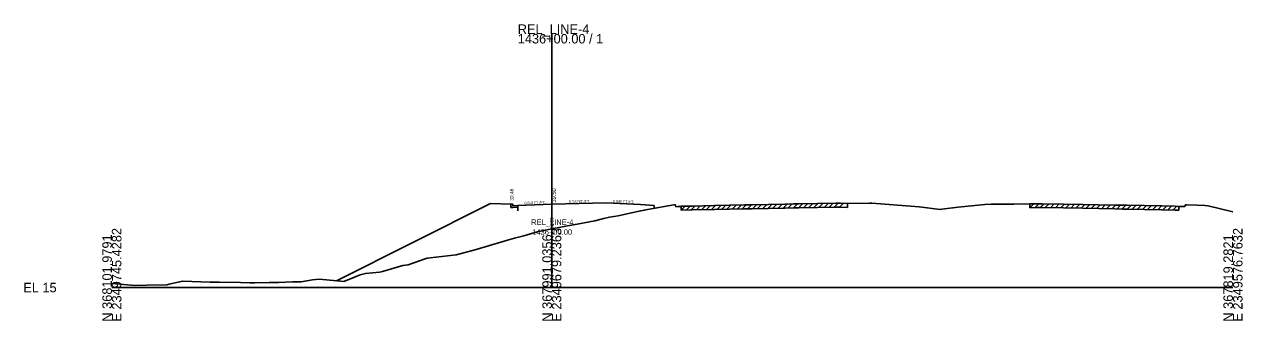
# Model space of a CAD drawing. Extents: x -26 to 2350146, y -10 to 368200.
# Drawn here: x 974.3 to 1332, y 7490.3 to 7577.2 of the extents above; entities that cross this region are included whole.
import ezdxf

# ---------------------------------------------------------------- set-up
doc = ezdxf.new("R2010")
doc.units = 0
for name, color, linetype in [('RD_GPK_XS_Cell', 7, 'Continuous'), ('RD_XS_CurbBase', 7, 'Continuous'), ('RD_XS_CurbFront', 7, 'Continuous'), ('RD_XS_CurbTop', 7, 'Continuous'), ('RD_XS_EarthShd', 7, 'Continuous'), ('RD_XS_ExGround', 7, 'Continuous'), ('RD_XS_ExPaveRet', 7, 'Continuous'), ('RD_XS_MatchLine', 7, 'Continuous'), ('RD_XS_Pave', 7, 'Continuous'), ('RD_XS_PaveShd', 7, 'Continuous'), ('RD_XS_TieSlope', 7, 'Continuous'), ('RD_XS_TX_Elev_EX', 7, 'Continuous'), ('RD_XS_TX_Elev_PR', 7, 'Continuous'), ('RD_XS_TX_Slope', 7, 'Continuous'), ('RD_XS_TX_Station', 7, 'Continuous'), ('RD_XS_TX_TOC', 7, 'Continuous')]:
    doc.layers.add(name, color=color, linetype=linetype)

msp = doc.modelspace()

# ---------------------------------------------------------------- linework, layer by layer
at = {"layer": 'RD_GPK_XS_Cell'}
for p, q in [((1129.19, 7500), (1129.19, 7574.41)), ((1000, 7500), (1129.19, 7500)), ((1129.19, 7500), (1329.19, 7500))]:
    msp.add_line(p, q, dxfattribs=at)
at = {"layer": 'RD_XS_CurbBase'}
for p, q in [((1117.19, 7524.5), (1117.19, 7523.5)), ((1117.19, 7523.5), (1117.69, 7523.5)), ((1117.69, 7523.5), (1119.19, 7523.58)), ((1119.19, 7522.52), (1119.19, 7523.58))]:
    msp.add_line(p, q, dxfattribs=at)
at = {"layer": 'RD_XS_CurbFront'}
msp.add_line((1119.19, 7523.58), (1119.19, 7524.08), dxfattribs=at)
at = {"layer": 'RD_XS_CurbTop'}
for p, q in [((1117.69, 7524.5), (1117.19, 7524.5)), ((1117.77, 7524), (1117.69, 7524.5)), ((1119.19, 7524.08), (1117.77, 7524)), ((1119.19, 7524.1), (1119.19, 7524.08))]:
    msp.add_line(p, q, dxfattribs=at)
at = {"layer": 'RD_XS_EarthShd'}
for p, q in [((1117.19, 7524.5), (1111.19, 7524.62)), ((1155.19, 7524.42), (1159.19, 7524.1))]:
    msp.add_line(p, q, dxfattribs=at)
at = {"layer": 'RD_XS_ExGround'}
msp.add_lwpolyline([(1000, 7501.23), (1006.95, 7500.56), (1010.29, 7500.75), (1016.12, 7500.81), (1016.78, 7500.96), (1020.71, 7501.91), (1028.9, 7501.55), (1031.62, 7501.55), (1037.79, 7501.45), (1040.49, 7501.41), (1041.96, 7501.42), (1046.16, 7501.5), (1048.93, 7501.45), (1053.02, 7501.68), (1054.52, 7501.72), (1055.57, 7501.73), (1058.89, 7502.26), (1060.89, 7502.42), (1063.02, 7502.27), (1068.15, 7501.82), (1071.22, 7503.03), (1072.9, 7503.74), (1074.44, 7504.15), (1078.54, 7504.53), (1079.06, 7504.65), (1079.45, 7504.76), (1085.42, 7506.5), (1086.96, 7506.71), (1092.01, 7508.4), (1092.63, 7508.63), (1099.4, 7509.37), (1101.11, 7509.58), (1106.27, 7510.97), (1109.62, 7511.97), (1116.21, 7513.88), (1118.22, 7514.5), (1120.93, 7515.17), (1124.89, 7516.34), (1129.19, 7517.19), (1133.78, 7518.08), (1136.61, 7518.59), (1141.84, 7519.57), (1144.47, 7520.28), (1146.12, 7520.65), (1148.67, 7521.09), (1155.24, 7522.47), (1156.36, 7522.72), (1156.75, 7522.79), (1157.32, 7522.9), (1165.04, 7524.25), (1165.47, 7524.24), (1165.63, 7523.73), (1166.22, 7523.75), (1166.88, 7523.78), (1167.12, 7523.86), (1169.98, 7523.92), (1170.43, 7523.93), (1176.92, 7524.06), (1185.73, 7524.23), (1186.33, 7524.25), (1188, 7524.29), (1197.56, 7524.48), (1200.16, 7524.54), (1201.71, 7524.56), (1212.65, 7524.74), (1213.91, 7524.72), (1215.98, 7524.69), (1222.43, 7524.8), (1222.87, 7524.8), (1223.18, 7524.78), (1235.82, 7523.74), (1237.06, 7523.64), (1243.26, 7522.94), (1243.75, 7523), (1248.53, 7523.61), (1256.32, 7524.34), (1258.19, 7524.51), (1264.83, 7524.51), (1269.58, 7524.58), (1271.3, 7524.59), (1273.12, 7524.61), (1279.42, 7524.51), (1285.04, 7524.41), (1294.52, 7524.21), (1296.8, 7524.15), (1298.12, 7524.13), (1308.2, 7523.95), (1312.23, 7523.86), (1313.3, 7523.83), (1313.49, 7523.78), (1315.03, 7523.75), (1315.22, 7524.23), (1315.61, 7524.24), (1318.64, 7524.18), (1320.94, 7524.12), (1321.89, 7523.99), (1329.19, 7522.21)], dxfattribs=at)
at = {"layer": 'RD_XS_ExPaveRet'}
for p, q in [((1167.12, 7522.72), (1168.29, 7523.88)), ((1167.12, 7522.72), (1167.12, 7523.86)), ((1168.62, 7522.75), (1169.79, 7523.92)), ((1170.12, 7522.78), (1171.29, 7523.95)), ((1170.43, 7522.79), (1176.92, 7522.92)), ((1171.62, 7522.81), (1172.79, 7523.98)), ((1173.12, 7522.84), (1174.29, 7524.01)), ((1174.62, 7522.87), (1175.79, 7524.04)), ((1176.12, 7522.9), (1177.29, 7524.07)), ((1176.92, 7522.92), (1185.73, 7523.09)), ((1177.62, 7522.93), (1178.79, 7524.1)), ((1179.12, 7522.96), (1180.29, 7524.13)), ((1180.62, 7522.99), (1181.79, 7524.15)), ((1182.12, 7523.02), (1183.29, 7524.18)), ((1183.62, 7523.05), (1184.79, 7524.21)), ((1185.12, 7523.08), (1186.29, 7524.25)), ((1185.73, 7523.09), (1186.33, 7523.1)), ((1186.33, 7523.1), (1188, 7523.15)), ((1186.62, 7523.11), (1187.79, 7524.28)), ((1188, 7523.15), (1197.56, 7523.34)), ((1188.12, 7523.15), (1189.29, 7524.32)), ((1189.62, 7523.18), (1190.79, 7524.35)), ((1191.12, 7523.21), (1192.29, 7524.38)), ((1192.62, 7523.24), (1193.79, 7524.41)), ((1194.12, 7523.27), (1195.29, 7524.44)), ((1195.62, 7523.3), (1196.79, 7524.47)), ((1197.12, 7523.33), (1198.29, 7524.5)), ((1197.56, 7523.34), (1200.16, 7523.39)), ((1198.62, 7523.36), (1199.79, 7524.53)), ((1200.12, 7523.39), (1201.28, 7524.55)), ((1200.16, 7523.39), (1201.71, 7523.42)), ((1201.62, 7523.42), (1202.78, 7524.58)), ((1201.71, 7523.42), (1212.65, 7523.59)), ((1203.12, 7523.44), (1204.28, 7524.6)), ((1204.62, 7523.46), (1205.78, 7524.63)), ((1206.12, 7523.49), (1207.28, 7524.65)), ((1207.62, 7523.51), (1208.78, 7524.67)), ((1209.12, 7523.54), (1210.28, 7524.7)), ((1210.62, 7523.56), (1211.78, 7524.72)), ((1212.12, 7523.58), (1213.27, 7524.73)), ((1212.65, 7523.59), (1213.91, 7523.58)), ((1213.62, 7523.58), (1214.74, 7524.71)), ((1213.91, 7523.58), (1215.98, 7523.54)), ((1215.98, 7524.69), (1215.98, 7523.54)), ((1269.58, 7523.43), (1270.73, 7524.59)), ((1269.58, 7523.43), (1269.58, 7524.58)), ((1269.58, 7523.43), (1271.3, 7523.45)), ((1271.08, 7523.45), (1272.23, 7524.6)), ((1271.3, 7523.45), (1273.12, 7523.47)), ((1272.58, 7523.46), (1273.72, 7524.6)), ((1273.12, 7523.47), (1279.42, 7523.37)), ((1274.08, 7523.45), (1275.2, 7524.58)), ((1275.58, 7523.43), (1276.7, 7524.55)), ((1277.08, 7523.4), (1278.2, 7524.53)), ((1278.58, 7523.38), (1279.7, 7524.5)), ((1279.42, 7523.37), (1285.04, 7523.27)), ((1280.08, 7523.35), (1281.2, 7524.48)), ((1281.58, 7523.33), (1282.7, 7524.45)), ((1283.08, 7523.3), (1284.2, 7524.43)), ((1284.58, 7523.28), (1285.7, 7524.4)), ((1285.04, 7523.27), (1294.52, 7523.06)), ((1286.08, 7523.25), (1287.2, 7524.37)), ((1287.58, 7523.22), (1288.7, 7524.33)), ((1289.08, 7523.18), (1290.2, 7524.3)), ((1290.58, 7523.15), (1291.7, 7524.27)), ((1292.08, 7523.12), (1293.2, 7524.23)), ((1293.58, 7523.08), (1294.7, 7524.2)), ((1294.52, 7523.06), (1296.8, 7523.01)), ((1295.08, 7523.05), (1296.2, 7524.17)), ((1296.58, 7523.02), (1297.7, 7524.14)), ((1296.8, 7523.01), (1298.12, 7522.99)), ((1298.08, 7522.99), (1299.2, 7524.11)), ((1298.12, 7522.99), (1308.2, 7522.81)), ((1299.58, 7522.96), (1300.7, 7524.09)), ((1301.08, 7522.94), (1302.2, 7524.06)), ((1302.58, 7522.91), (1303.7, 7524.03)), ((1304.08, 7522.88), (1305.2, 7524)), ((1305.58, 7522.85), (1306.7, 7523.98)), ((1307.08, 7522.83), (1308.2, 7523.95)), ((1308.58, 7522.8), (1309.69, 7523.92)), ((1310.08, 7522.76), (1311.19, 7523.88)), ((1311.58, 7522.73), (1312.69, 7523.84)), ((1313.3, 7523.83), (1313.3, 7522.69)), ((1167.12, 7522.72), (1169.98, 7522.78)), ((1169.98, 7522.78), (1170.43, 7522.79)), ((1308.2, 7522.81), (1312.23, 7522.71)), ((1312.23, 7522.71), (1313.3, 7522.69))]:
    msp.add_line(p, q, dxfattribs=at)
at = {"layer": 'RD_XS_MatchLine'}
msp.add_line((1159.19, 7523.23), (1159.19, 7524.1), dxfattribs=at)
at = {"layer": 'RD_XS_Pave'}
for q in [(1119.19, 7524.1), (1145.19, 7524.82)]:
    msp.add_line((1129.19, 7524.5), q, dxfattribs=at)
at = {"layer": 'RD_XS_PaveShd'}
msp.add_line((1145.19, 7524.82), (1155.19, 7524.42), dxfattribs=at)
at = {"layer": 'RD_XS_TieSlope'}
msp.add_line((1111.19, 7524.62), (1065.98, 7502.01), dxfattribs=at)

# ---------------------------------------------------------------- texts
at = {"layer": 'RD_GPK_XS_Cell'}
for s, p in [('REL_LINE-4', (1119.19, 7574.41)), ('1436+00.00 / 1', (1119.19, 7571.61)), ('EL 15', (974, 7498.6))]:
    msp.add_text(s, height=2.8, dxfattribs=at).set_placement(p)
for s, p in [('E 2349745.4282', (1002.8, 7490)), ('E 2349679.2363', (1131.99, 7490)), ('E 2349576.7632', (1331.99, 7490)), ('N 368101.9791', (1000, 7490)), ('N 367991.0356', (1129.19, 7490)), ('N 367819.2821', (1329.19, 7490))]:
    msp.add_text(s, height=2.8, rotation=90, dxfattribs=at).set_placement(p)
at = {"layer": 'RD_XS_TX_Elev_EX'}
msp.add_text('32.19', height=1, rotation=90, dxfattribs=at).set_placement((1129.69, 7517.19))
at = {"layer": 'RD_XS_TX_Elev_PR'}
for s, height, p in [('39.48', 1, (1117.94, 7525.5)), (' 39.50', 1.2, (1130.39, 7524.5))]:
    msp.add_text(s, height=height, rotation=90, dxfattribs=at).set_placement(p)
at = {"layer": 'RD_XS_TX_Slope'}
for s, rotation, p in [('0.040 FT./FT.', 2.2906, (1121.15, 7524.43)), ('0.020 FT./FT.', 1.1458, (1134.16, 7524.85)), ('0.040 FT./FT.', 357.7094, (1147.17, 7524.99))]:
    msp.add_text(s, height=0.75, rotation=rotation, dxfattribs=at).set_placement(p)
at = {"layer": 'RD_XS_TX_Station'}
for s, p in [('REL_LINE-4', (1123.12, 7518.39)), ('1436+00.00', (1123.42, 7515.49))]:
    msp.add_text(s, height=1.6, dxfattribs=at).set_placement(p)
at = {"layer": 'RD_XS_TX_TOC'}
msp.add_text('TOCLT', height=0.05, dxfattribs=at).set_placement((1117.74, 7524.45))

doc.saveas('drawing.dxf')
